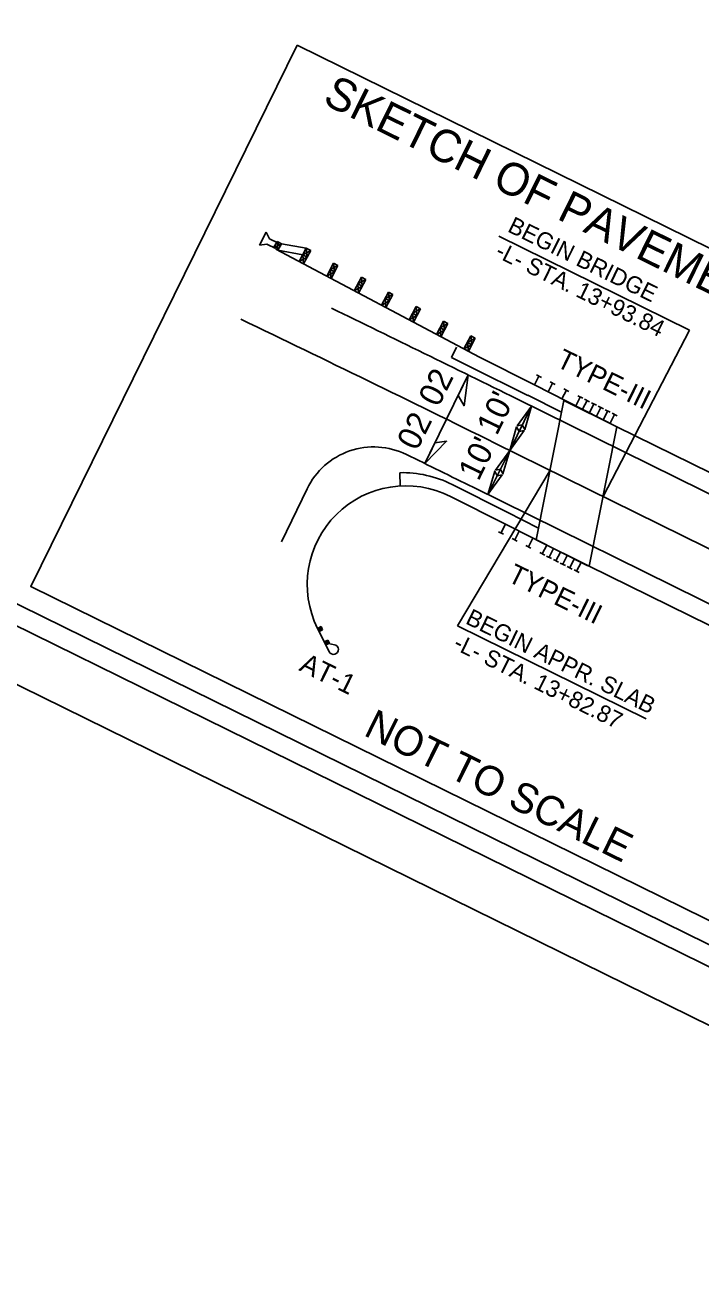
# Model space of a CAD drawing. Extents: x 1428420 to 1430540, y 857897 to 859622.
# Drawn here: x 1429472.5 to 1429729.3, y 857896.7 to 858374.2 of the extents above; entities that cross this region are included whole.
import ezdxf

# ---------------------------------------------------------------- set-up
doc = ezdxf.new("R2010")
doc.units = 0
for name, color, linetype in [('Default', 7, 'Continuous'), ('Prop Approach Slab Hatching', 7, 'Continuous'), ('Prop Conc Shoulder Berm Gutter', 7, 'Continuous'), ('Prop Dimension', 7, 'Continuous'), ('Prop Dimension Text', 7, 'Continuous'), ('Prop EOT', 7, 'Continuous'), ('Prop Guardrail', 7, 'Continuous'), ('Prop Guardrail Anchor Unit CELL', 7, 'Continuous'), ('Prop Horizontal Alignment', 7, 'Continuous'), ('Prop Horizontal Alignment Curve and Spiral Data', 7, 'Continuous'), ('Prop Horizontal Alignment Station Label', 7, 'Continuous'), ('Prop Roadway Bridge', 7, 'Continuous'), ('Prop Structure Anchor Unit CELL', 7, 'Continuous'), ('Prop Superelevation  Arrow CELL', 7, 'Continuous'), ('Prop Superelevation Label', 7, 'Continuous'), ('Prop Terminator CELL', 7, 'Continuous'), ('Sheet Data Text CELL', 7, 'Continuous'), ('Sheet Plan CELL', 7, 'Continuous'), ('Sheet Plot Border Inside CELL', 7, 'Continuous'), ('Sheet Plot Border Outside CELL', 7, 'Continuous'), ('Sheet Profile CELL', 7, 'Continuous')]:
    doc.layers.add(name, color=color, linetype=linetype)

msp = doc.modelspace()

# ---------------------------------------------------------------- linework, layer by layer
at = {"layer": 'Default'}
for p, q in [((1429654.3, 858180.72), (1429652.39, 858181.69)), ((1429655.04, 858184.55), (1429653.34, 858181.2)), ((1429686.42, 858168.7), (1429655.04, 858184.55)), ((1429660.27, 858181.91), (1429658.58, 858178.56)), ((1429659.53, 858178.08), (1429657.62, 858179.05)), ((1429664.76, 858175.44), (1429662.85, 858176.4)), ((1429665.5, 858179.27), (1429663.81, 858175.92)), ((1429670.73, 858176.62), (1429669.04, 858173.28)), ((1429669.99, 858172.79), (1429668.08, 858173.76)), ((1429672.61, 858171.47), (1429670.69, 858172.44)), ((1429673.34, 858175.3), (1429671.65, 858171.96)), ((1429675.22, 858170.15), (1429673.31, 858171.12)), ((1429675.96, 858173.98), (1429674.27, 858170.64)), ((1429678.57, 858172.66), (1429676.88, 858169.32)), ((1429681.19, 858171.34), (1429679.5, 858167.99)), ((1429677.84, 858168.83), (1429675.92, 858169.8)), ((1429680.45, 858167.51), (1429678.54, 858168.48)), ((1429683.07, 858166.19), (1429681.15, 858167.16)), ((1429683.8, 858170.02), (1429682.11, 858166.67))]:
    msp.add_line(p, q, dxfattribs=at)
at = {"layer": 'Prop Approach Slab Hatching'}
for p, q in [((1429677.29, 858231.57), (1429666.74, 858178.59)), ((1429697.46, 858221.59), (1429677.29, 858231.57)), ((1429686.92, 858168.6), (1429697.46, 858221.59)), ((1429666.74, 858178.59), (1429686.92, 858168.6))]:
    msp.add_line(p, q, dxfattribs=at)
at = {"layer": 'Prop Conc Shoulder Berm Gutter'}
for p, q in [((1429636.43, 858251.77), (1429634.51, 858247.84)), ((1429634.51, 858247.84), (1429641.67, 858244.29)), ((1429641.67, 858244.29), (1429663.53, 858233.5)), ((1429663.53, 858233.51), (1429676.41, 858227.13)), ((1429614.85, 858204.12), (1429614.98, 858199.08)), ((1429634.78, 858199.63), (1429655.7, 858189.07)), ((1429655.7, 858189.07), (1429667.67, 858183.02))]:
    msp.add_line(p, q, dxfattribs=at)
msp.add_arc((1429615.9, 858162.26), 41.87, 63.2012, 91.4314, dxfattribs=at)
at = {"layer": 'Prop Dimension'}
for p, q in [((1429664.97, 858229.43), (1429656.69, 858212.6)), ((1429656.69, 858212.6), (1429648.41, 858195.78))]:
    msp.add_line(p, q, dxfattribs=at)
at = {"layer": 'Prop EOT'}
for p, q in [((1429659.35, 858232.2), (1429905.96, 858110.54)), ((1429569.9, 858177.81), (1429579.69, 858198.04)), ((1429642.76, 858198.57), (1429953.37, 858045.34))]:
    msp.add_line(p, q, dxfattribs=at)
for centre, radius, start, end in [((1424673.97, 848126.22), 11268.75, 63.742405, 64.140805), ((1429605, 858185.79), 28.13, 63.8867, 154.1799), ((1424673.97, 848126.22), 11231.25, 63.742405, 63.886689)]:
    msp.add_arc(centre, radius, start, end, dxfattribs=at)
at = {"layer": 'Prop Guardrail'}
for p, q in [((1429666.08, 858237.44), (1429645.16, 858248)), ((1429634.12, 858195.12), (1429655.04, 858184.55))]:
    msp.add_line(p, q, dxfattribs=at)
msp.add_arc((1429617.21, 858161.64), 37.5, 63.2012, 206.4407, dxfattribs=at)
at = {"layer": 'Prop Guardrail Anchor Unit CELL'}
for p, q in [((1429561.62, 858290.53), (1429564.11, 858295.45)), ((1429564.11, 858295.45), (1429565.35, 858293.01)), ((1429564.32, 858290.97), (1429561.62, 858290.53)), ((1429567.74, 858289.24), (1429564.32, 858290.97)), ((1429565.35, 858293.01), (1429568.78, 858291.28)), ((1429566.9, 858289.52), (1429568.22, 858292.01)), ((1429566.9, 858289.52), (1429569.87, 858291.13)), ((1429568.26, 858290.26), (1429567.74, 858289.24)), ((1429569.87, 858291.13), (1429568.22, 858292.01)), ((1429568.22, 858292.01), (1429568.55, 858288.64)), ((1429568.78, 858291.28), (1429568.26, 858290.26)), ((1429568.55, 858288.64), (1429569.87, 858291.13)), ((1429569.87, 858291.13), (1429569.04, 858291.57)), ((1429579.36, 858289.41), (1429569.87, 858291.13)), ((1429645.16, 858248), (1429567.73, 858289.08)), ((1429578.02, 858286.88), (1429568.55, 858288.64)), ((1429576.67, 858284.34), (1429579.36, 858289.41)), ((1429579.67, 858286), (1429576.67, 858284.34)), ((1429578.02, 858286.88), (1429581.02, 858288.53)), ((1429579.67, 858286), (1429578.02, 858286.88)), ((1429578.33, 858283.46), (1429578.02, 858286.88)), ((1429578.33, 858283.46), (1429581.02, 858288.53)), ((1429581.02, 858288.53), (1429579.36, 858289.41)), ((1429579.36, 858289.41), (1429579.67, 858286)), ((1429587.11, 858278.8), (1429589.74, 858283.77)), ((1429588.43, 858281.29), (1429591.4, 858282.89)), ((1429590.08, 858280.41), (1429588.43, 858281.29)), ((1429588.77, 858277.92), (1429588.43, 858281.29)), ((1429588.77, 858277.92), (1429591.4, 858282.89)), ((1429591.4, 858282.89), (1429589.74, 858283.77)), ((1429589.74, 858283.77), (1429590.08, 858280.41)), ((1429590.08, 858280.41), (1429587.11, 858278.8)), ((1429597.55, 858273.26), (1429600.3, 858278.46)), ((1429598.93, 858275.86), (1429601.96, 858277.58)), ((1429599.2, 858272.38), (1429601.96, 858277.58)), ((1429601.96, 858277.58), (1429600.3, 858278.46)), ((1429600.3, 858278.46), (1429600.58, 858274.98)), ((1429600.58, 858274.98), (1429597.55, 858273.26)), ((1429600.58, 858274.98), (1429598.93, 858275.86)), ((1429599.2, 858272.38), (1429598.93, 858275.86)), ((1429607.98, 858267.73), (1429610.65, 858272.75)), ((1429609.32, 858270.24), (1429612.31, 858271.88)), ((1429609.64, 858266.85), (1429612.31, 858271.88)), ((1429612.31, 858271.88), (1429610.65, 858272.75)), ((1429610.65, 858272.75), (1429610.97, 858269.36)), ((1429610.97, 858269.36), (1429607.98, 858267.73)), ((1429609.64, 858266.85), (1429607.98, 858267.73)), ((1429610.97, 858269.36), (1429609.32, 858270.24)), ((1429609.64, 858266.85), (1429609.32, 858270.24)), ((1429618.42, 858262.19), (1429621.1, 858267.24)), ((1429619.76, 858264.72), (1429622.76, 858266.36)), ((1429620.08, 858261.31), (1429622.76, 858266.36)), ((1429622.76, 858266.36), (1429621.1, 858267.24)), ((1429621.1, 858267.24), (1429621.42, 858263.84)), ((1429621.42, 858263.84), (1429618.42, 858262.19)), ((1429621.42, 858263.84), (1429619.76, 858264.72)), ((1429620.08, 858261.31), (1429619.76, 858264.72)), ((1429628.86, 858256.65), (1429631.54, 858261.71)), ((1429633.2, 858260.83), (1429631.54, 858261.71)), ((1429631.54, 858261.71), (1429631.85, 858258.3)), ((1429631.85, 858258.3), (1429628.86, 858256.65)), ((1429630.2, 858259.18), (1429633.2, 858260.83)), ((1429631.85, 858258.3), (1429630.2, 858259.18)), ((1429630.51, 858255.77), (1429630.2, 858259.18)), ((1429630.51, 858255.77), (1429633.2, 858260.83)), ((1429639.3, 858251.12), (1429641.93, 858256.09)), ((1429639.3, 858251.12), (1429640.61, 858253.6)), ((1429642.27, 858252.72), (1429639.3, 858251.12)), ((1429640.61, 858253.6), (1429643.59, 858255.21)), ((1429642.27, 858252.72), (1429640.61, 858253.6)), ((1429640.61, 858253.6), (1429640.95, 858250.24)), ((1429640.95, 858250.24), (1429643.59, 858255.21)), ((1429643.59, 858255.21), (1429641.93, 858256.09)), ((1429641.93, 858256.09), (1429642.27, 858252.72)), ((1429640.95, 858250.24), (1429639.3, 858251.12)), ((1429584.99, 858145.62), (1429583.63, 858144.95)), ((1429583.63, 858144.95), (1429586.59, 858139)), ((1429583.63, 858144.95), (1429584.22, 858143.77)), ((1429583.63, 858144.95), (1429585.57, 858144.45)), ((1429584.22, 858143.77), (1429584.99, 858145.62)), ((1429584.22, 858143.77), (1429585.57, 858144.45)), ((1429585.57, 858144.45), (1429584.99, 858145.62)), ((1429587.53, 858140.51), (1429586.17, 858139.84)), ((1429586.17, 858139.84), (1429586.76, 858138.66)), ((1429586.17, 858139.84), (1429588.11, 858139.34)), ((1429586.65, 858138.88), (1429586.53, 858139.11)), ((1429586.65, 858138.88), (1429586.53, 858139.11)), ((1429586.59, 858139), (1429588.02, 858136.11)), ((1429586.76, 858138.66), (1429587.53, 858140.51)), ((1429586.76, 858138.66), (1429588.11, 858139.34)), ((1429586.76, 858138.66), (1429587.35, 858138.96)), ((1429586.76, 858138.66), (1429587.35, 858138.96)), ((1429588.11, 858139.34), (1429587.53, 858140.51)), ((1429590.02, 858138.77), (1429587.79, 858139.18))]:
    msp.add_line(p, q, dxfattribs=at)
msp.add_ellipse((1429589.69, 858136.94), major_axis=(1.67, 0.83), ratio=0.995379, start_param=3.141593, end_param=7.214552, dxfattribs=at)
at = {"layer": 'Prop Horizontal Alignment'}
msp.add_line((1429651.06, 858215.38), (1429897.67, 858093.73), dxfattribs=at)
msp.add_arc((1424673.97, 848126.22), 11250, 63.742405, 64.2894, dxfattribs=at)
at = {"layer": 'Prop Horizontal Alignment Curve and Spiral Data'}
msp.add_lwpolyline([(1429575.84, 858366.59), (1430022.18, 858146.96), (1429920.93, 857941.2), (1429474.59, 858160.83)], close=True, dxfattribs=at)
at = {"layer": 'Prop Roadway Bridge'}
for p, q in [((1429697.46, 858221.59), (1429686.92, 858168.6)), ((1429697.46, 858221.59), (1429831.99, 858155.23)), ((1429686.92, 858168.6), (1429821.44, 858102.24))]:
    msp.add_line(p, q, dxfattribs=at)
at = {"layer": 'Prop Structure Anchor Unit CELL'}
for p, q in [((1429666.08, 858237.44), (1429667.77, 858240.78)), ((1429668.73, 858240.3), (1429666.82, 858241.27)), ((1429671.31, 858234.8), (1429673, 858238.14)), ((1429673.96, 858237.66), (1429672.05, 858238.63)), ((1429697.46, 858221.59), (1429666.08, 858237.44)), ((1429676.54, 858232.15), (1429678.23, 858235.5)), ((1429679.19, 858235.02), (1429677.28, 858235.99)), ((1429684.42, 858232.37), (1429682.51, 858233.34)), ((1429681.77, 858229.51), (1429683.46, 858232.86)), ((1429684.39, 858228.19), (1429686.08, 858231.54)), ((1429687.04, 858231.05), (1429685.12, 858232.02)), ((1429687, 858226.87), (1429688.69, 858230.22)), ((1429689.65, 858229.73), (1429687.74, 858230.7)), ((1429689.62, 858225.55), (1429691.31, 858228.9)), ((1429692.27, 858228.41), (1429690.35, 858229.38)), ((1429692.23, 858224.23), (1429693.92, 858227.58)), ((1429694.88, 858227.09), (1429692.97, 858228.06)), ((1429694.85, 858222.91), (1429696.54, 858226.25)), ((1429697.5, 858225.77), (1429695.58, 858226.74))]:
    msp.add_line(p, q, dxfattribs=at)
at = {"layer": 'Prop Superelevation  Arrow CELL'}
for p in [(1429640.93, 858241.27), (1429624.37, 858207.62)]:
    msp.add_line(p, (1429632.65, 858224.44), dxfattribs=at)
for points in [[(1429640.93, 858241.27), (1429639.33, 858229.52), (1429637.1, 858233.49)], [(1429624.37, 858207.62), (1429632.7, 858216.06), (1429628.2, 858215.4)]]:
    msp.add_lwpolyline(points, close=True, dxfattribs=at)
at = {"layer": 'Prop Terminator CELL'}
for points in [[(1429659.54, 858221.94), (1429664.97, 858229.43), (1429662.38, 858220.49), (1429661.44, 858222.25)], [(1429662.12, 858220.09), (1429656.69, 858212.6), (1429659.28, 858221.54), (1429660.22, 858219.78)], [(1429651.26, 858205.12), (1429656.69, 858212.6), (1429654.1, 858203.67), (1429653.16, 858205.43)], [(1429653.85, 858203.26), (1429648.41, 858195.78), (1429651.01, 858204.72), (1429651.95, 858202.96)]]:
    msp.add_lwpolyline(points, close=True, dxfattribs=at)
at = {"layer": 'Sheet Data Text CELL'}
for p, q in [((1429725.05, 858258.29), (1429652.55, 858293.96)), ((1429692.19, 858195.09), (1429725.05, 858258.29)), ((1429672, 858205.05), (1429636.78, 858145.92)), ((1429708.53, 858110.61), (1429636.78, 858145.92))]:
    msp.add_line(p, q, dxfattribs=at)
at = {"layer": 'Sheet Plan CELL'}
for points in [[(1430386.67, 858862), (1429040.75, 859524.27), (1428581.58, 858591.12), (1429927.48, 857928.86)], [(1428581.58, 858591.12), (1429040.71, 859524.26), (1430207.15, 858950.35), (1430140.91, 858815.69), (1430320.39, 858727.37), (1429927.48, 857928.86)]]:
    msp.add_lwpolyline(points, close=True, dxfattribs=at)
at = {"layer": 'Sheet Plot Border Inside CELL'}
msp.add_lwpolyline([(1428440.55, 858652.15), (1429935.37, 857916.62), (1430401.17, 858863.21), (1428906.33, 859598.76)], close=True, dxfattribs=at)
at = {"layer": 'Sheet Plot Border Outside CELL'}
msp.add_lwpolyline([(1428420.05, 858639.94), (1429930.59, 857896.67), (1430414.03, 858879.17), (1428903.5, 859622.44)], close=True, dxfattribs=at)

# ---------------------------------------------------------------- texts
at = {"layer": 'Prop Dimension Text'}
for p in [(1429651.75, 858217.89), (1429644.8, 858200.59)]:
    msp.add_text("10'", height=9, rotation=63.8001, dxfattribs=at).set_placement(p)
at = {"layer": 'Prop Guardrail Anchor Unit CELL'}
for s, p in [('TYPE-III', (1429673.91, 858244.69)), ('TYPE-III', (1429655.4, 858163.06)), ('AT-1', (1429576.24, 858129.13))]:
    msp.add_text(s, height=7.5, rotation=333.8001, dxfattribs=at).set_placement(p)
at = {"layer": 'Prop Horizontal Alignment Station Label'}
msp.add_text('SKETCH OF PAVEMENT/BRIDGE RELATIONSHIP', height=12.375, rotation=333.8001, dxfattribs=at).set_placement((1429585.13, 858344.55))
at = {"layer": 'Prop Superelevation Label'}
for p in [(1429629.59, 858228.69), (1429621.43, 858212.1)]:
    msp.add_text('02', height=9, rotation=63.3554, dxfattribs=at).set_placement(p)
at = {"layer": 'Sheet Data Text CELL'}
for s, p in [('BEGIN BRIDGE', (1429655.48, 858295.9)), ('-L- STA. 13+93.84', (1429650.79, 858286.36)), ('BEGIN APPR. SLAB', (1429639.48, 858146.95)), ('-L- STA. 13+82.87', (1429634.79, 858137.42))]:
    msp.add_text(s, height=6.375, rotation=333.8001, dxfattribs=at).set_placement(p)
at = {"layer": 'Sheet Profile CELL'}
msp.add_text('NOT TO SCALE', height=11.25, rotation=333.8001, dxfattribs=at).set_placement((1429600.7, 858104.54))

doc.saveas('drawing.dxf')
